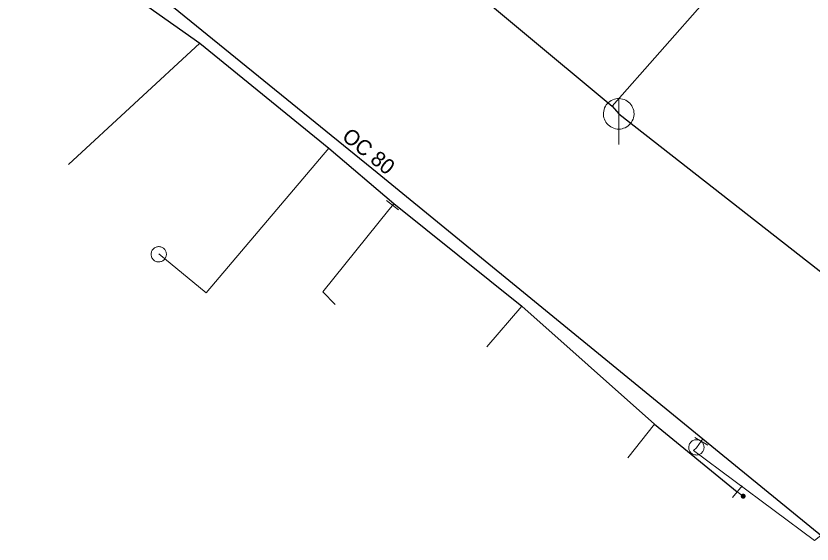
# Model space of a CAD drawing. Extents: x -807203 to -805207, y -993656 to -992505.
# Drawn here: x -806253.1 to -806201.1, y -993114.2 to -993079.6 of the extents above; entities that cross this region are included whole.
import ezdxf

# ---------------------------------------------------------------- set-up
doc = ezdxf.new("R2010")
doc.units = 0
doc.header["$LTSCALE"] = 0.4
for name, color, linetype, lineweight in [('1', 7, 'Continuous', 13), ('11', 7, 'Continuous', 13), ('13', 7, 'Continuous', 13), ('14', 7, 'Continuous', 25), ('17', 7, 'Continuous', 25), ('22', 7, 'Continuous', 13), ('23', 7, 'Continuous', 13), ('34', 7, 'Continuous', 13), ('9', 7, 'Continuous', 13)]:
    doc.layers.add(name, color=color, linetype=linetype, lineweight=lineweight)

msp = doc.modelspace()

# ---------------------------------------------------------------- linework, layer by layer
at = {"layer": '11'}
msp.add_line((-806202.545, -993072.334), (-806214.182, -993085.525), dxfattribs=at)
at = {"layer": '13'}
for p, q in [((-806241.126, -993081.403), (-806249.708, -993089.354)), ((-806220.091, -993098.618), (-806222.371, -993101.277)), ((-806211.407, -993106.321), (-806213.149, -993108.524)), ((-806208.354, -993107.448), (-806208.673, -993107.877))]:
    msp.add_line(p, q, dxfattribs=at)
for points in [[(-806232.688, -993088.282), (-806240.721, -993097.734), (-806243.812, -993095.184)], [(-806228.53, -993092.005), (-806228.541, -993092.017), (-806228.771, -993092.304), (-806233.083, -993097.67), (-806232.282, -993098.499)], [(-806208.673, -993107.877), (-806208.857, -993108.048), (-806200.958, -993113.93), (-806188.421, -993104.047)]]:
    msp.add_lwpolyline(points, dxfattribs=at)
at = {"layer": '14', "lineweight": 13}
for p, q in [((-806208.251, -993107.276), (-806208.354, -993107.448)), ((-806206.008, -993110.745), (-806205.613, -993111.035))]:
    msp.add_line(p, q, dxfattribs=at)
at = {"layer": '14'}
for points in [[(-806254.43, -993051.92), (-806244.407, -993060.288), (-806237.672, -993065.911), (-806232.281, -993070.413), (-806214.182, -993085.525), (-806213.75, -993086.03)], [(-806213.75, -993086.03), (-806174.365, -993116.849), (-806173.301, -993117.667)]]:
    msp.add_lwpolyline(points, dxfattribs=at)
at = {"layer": '14', "lineweight": 13}
msp.add_lwpolyline([(-806228.53, -993092.005), (-806228.521, -993091.993), (-806228.441, -993091.894)], dxfattribs=at)
at = {"layer": '17'}
for points in [[(-806264, -993062.975), (-806257.908, -993068.451), (-806254.907, -993071.059), (-806252.861, -993072.806), (-806252.697, -993072.945), (-806252.545, -993073.07), (-806250.353, -993074.879), (-806241.125, -993081.403), (-806232.688, -993088.282), (-806228.441, -993091.894), (-806220.09, -993098.618), (-806211.407, -993106.321), (-806206.008, -993110.745)], [(-806260.066, -993064.828), (-806248.392, -993074.528), (-806229.53, -993089.861), (-806208.251, -993107.276), (-806200.433, -993113.675), (-806198.425, -993115.318), (-806170.996, -993137.161), (-806169.414, -993138.403), (-806155.574, -993149.442), (-806086.497, -993204.202), (-806063.424, -993223.055)]]:
    msp.add_lwpolyline(points, dxfattribs=at)
at = {"layer": '22'}
msp.add_line((-806213.75, -993088.03), (-806213.749, -993085.03), dxfattribs=at)
msp.add_lwpolyline([(-806212.75, -993086.03), (-806212.755, -993085.921), (-806212.773, -993085.813), (-806212.803, -993085.707), (-806212.843, -993085.606), (-806212.895, -993085.509), (-806212.957, -993085.419), (-806213.029, -993085.336), (-806213.109, -993085.262), (-806213.197, -993085.196), (-806213.291, -993085.141), (-806213.391, -993085.096), (-806213.496, -993085.063), (-806213.603, -993085.041), (-806213.712, -993085.031), (-806213.822, -993085.033), (-806213.93, -993085.047), (-806214.037, -993085.072), (-806214.14, -993085.109), (-806214.238, -993085.158), (-806214.33, -993085.216), (-806214.416, -993085.285), (-806214.493, -993085.362), (-806214.562, -993085.448), (-806214.621, -993085.54), (-806214.669, -993085.638), (-806214.706, -993085.741), (-806214.732, -993085.848), (-806214.746, -993085.956), (-806214.749, -993086.066), (-806214.739, -993086.175), (-806214.718, -993086.282), (-806214.684, -993086.386), (-806214.64, -993086.486), (-806214.585, -993086.581), (-806214.519, -993086.669), (-806214.445, -993086.749), (-806214.362, -993086.821), (-806214.272, -993086.883), (-806214.176, -993086.935), (-806214.074, -993086.976), (-806213.969, -993087.006), (-806213.861, -993087.024), (-806213.751, -993087.03), (-806213.642, -993087.024), (-806213.534, -993087.006), (-806213.429, -993086.977), (-806213.327, -993086.936), (-806213.23, -993086.884), (-806213.14, -993086.822), (-806213.057, -993086.751), (-806212.982, -993086.671), (-806212.917, -993086.583), (-806212.861, -993086.489), (-806212.817, -993086.389), (-806212.783, -993086.285), (-806212.761, -993086.177), (-806212.751, -993086.068)], close=True, dxfattribs=at)
at = {"layer": '23'}
for points in [[(-806243.495, -993094.826), (-806243.538, -993094.795), (-806243.583, -993094.769), (-806243.631, -993094.749), (-806243.681, -993094.733), (-806243.731, -993094.722), (-806243.784, -993094.717), (-806243.836, -993094.717), (-806243.888, -993094.723), (-806243.939, -993094.734), (-806243.989, -993094.75), (-806244.037, -993094.771), (-806244.083, -993094.798), (-806244.125, -993094.828), (-806244.162, -993094.863), (-806244.198, -993094.901), (-806244.229, -993094.946), (-806244.255, -993094.989), (-806244.276, -993095.039), (-806244.292, -993095.087), (-806244.304, -993095.138), (-806244.308, -993095.192), (-806244.308, -993095.244), (-806244.302, -993095.297), (-806244.292, -993095.347), (-806244.275, -993095.396), (-806244.253, -993095.445), (-806244.227, -993095.489), (-806244.196, -993095.531), (-806244.16, -993095.57), (-806244.122, -993095.605), (-806244.08, -993095.636), (-806244.034, -993095.662), (-806243.986, -993095.684), (-806243.937, -993095.7), (-806243.886, -993095.709), (-806243.834, -993095.715), (-806243.781, -993095.715), (-806243.728, -993095.709), (-806243.678, -993095.698)], [(-806244.276, -993095.039), (-806244.292, -993095.087), (-806244.304, -993095.138), (-806244.308, -993095.192), (-806244.308, -993095.244), (-806244.302, -993095.297), (-806244.292, -993095.347), (-806244.275, -993095.396), (-806244.253, -993095.445), (-806244.227, -993095.489), (-806244.196, -993095.531), (-806244.16, -993095.57), (-806244.122, -993095.605), (-806244.08, -993095.636), (-806244.034, -993095.662), (-806243.986, -993095.684), (-806243.937, -993095.7), (-806243.886, -993095.709), (-806243.834, -993095.715), (-806243.781, -993095.715), (-806243.728, -993095.709), (-806243.678, -993095.698), (-806243.629, -993095.683), (-806243.58, -993095.66), (-806243.535, -993095.635), (-806243.493, -993095.603), (-806243.455, -993095.568), (-806243.42, -993095.53), (-806243.39, -993095.487), (-806243.363, -993095.442), (-806243.341, -993095.393), (-806243.326, -993095.344), (-806243.315, -993095.292), (-806243.309, -993095.241), (-806243.311, -993095.188), (-806243.315, -993095.137), (-806243.326, -993095.086), (-806243.342, -993095.035), (-806243.364, -993094.987), (-806243.39, -993094.942)], [(-806243.678, -993095.698), (-806243.629, -993095.683), (-806243.58, -993095.66), (-806243.535, -993095.635), (-806243.493, -993095.603), (-806243.455, -993095.568), (-806243.42, -993095.53), (-806243.39, -993095.487), (-806243.363, -993095.442), (-806243.341, -993095.393), (-806243.326, -993095.344), (-806243.315, -993095.292), (-806243.309, -993095.241), (-806243.311, -993095.188), (-806243.315, -993095.137), (-806243.326, -993095.086), (-806243.342, -993095.035), (-806243.364, -993094.987), (-806243.39, -993094.942), (-806243.422, -993094.9), (-806243.456, -993094.862), (-806243.495, -993094.826), (-806243.538, -993094.795), (-806243.583, -993094.769), (-806243.631, -993094.749), (-806243.681, -993094.733), (-806243.731, -993094.722), (-806243.784, -993094.717), (-806243.836, -993094.717), (-806243.888, -993094.723), (-806243.939, -993094.734), (-806243.989, -993094.75), (-806244.037, -993094.771), (-806244.083, -993094.798), (-806244.125, -993094.828), (-806244.162, -993094.863), (-806244.198, -993094.901), (-806244.229, -993094.946), (-806244.255, -993094.989), (-806244.276, -993095.039)], [(-806243.39, -993094.942), (-806243.422, -993094.9), (-806243.456, -993094.862), (-806243.495, -993094.826)], [(-806208.209, -993108.025), (-806208.193, -993107.977), (-806208.181, -993107.926), (-806208.176, -993107.872), (-806208.176, -993107.82), (-806208.181, -993107.767), (-806208.191, -993107.716), (-806208.207, -993107.667), (-806208.229, -993107.619), (-806208.254, -993107.574), (-806208.285, -993107.532), (-806208.321, -993107.493), (-806208.359, -993107.457), (-806208.4, -993107.426), (-806208.446, -993107.4), (-806208.494, -993107.378), (-806208.543, -993107.361), (-806208.594, -993107.352), (-806208.646, -993107.346), (-806208.699, -993107.345), (-806208.751, -993107.35), (-806208.802, -993107.361), (-806208.851, -993107.376), (-806208.9, -993107.398), (-806208.945, -993107.423), (-806208.988, -993107.455), (-806209.026, -993107.489), (-806209.062, -993107.527), (-806209.092, -993107.57), (-806209.119, -993107.615), (-806209.141, -993107.663), (-806209.157, -993107.712), (-806209.168, -993107.764), (-806209.175, -993107.815), (-806209.173, -993107.868), (-806209.17, -993107.919), (-806209.159, -993107.97), (-806209.143, -993108.021), (-806209.121, -993108.069), (-806209.095, -993108.114)], [(-806208.802, -993107.361), (-806208.851, -993107.376), (-806208.9, -993107.398), (-806208.945, -993107.423), (-806208.988, -993107.455), (-806209.026, -993107.489), (-806209.062, -993107.527), (-806209.092, -993107.57), (-806209.119, -993107.615), (-806209.141, -993107.663), (-806209.157, -993107.712), (-806209.168, -993107.764), (-806209.175, -993107.815), (-806209.173, -993107.868), (-806209.17, -993107.919), (-806209.159, -993107.97), (-806209.143, -993108.021), (-806209.121, -993108.069), (-806209.095, -993108.114), (-806209.064, -993108.156), (-806209.03, -993108.195), (-806208.992, -993108.231), (-806208.95, -993108.263), (-806208.904, -993108.289), (-806208.857, -993108.309), (-806208.807, -993108.326), (-806208.756, -993108.337), (-806208.703, -993108.342), (-806208.651, -993108.343), (-806208.6, -993108.338), (-806208.549, -993108.327), (-806208.499, -993108.312), (-806208.45, -993108.291), (-806208.404, -993108.264), (-806208.362, -993108.234), (-806208.324, -993108.2), (-806208.288, -993108.162), (-806208.257, -993108.118), (-806208.231, -993108.074), (-806208.209, -993108.025)], [(-806208.992, -993108.231), (-806208.95, -993108.263), (-806208.904, -993108.289), (-806208.857, -993108.309), (-806208.807, -993108.326), (-806208.756, -993108.337), (-806208.703, -993108.342), (-806208.651, -993108.343), (-806208.6, -993108.338), (-806208.549, -993108.327), (-806208.499, -993108.312), (-806208.45, -993108.291), (-806208.404, -993108.264), (-806208.362, -993108.234), (-806208.324, -993108.2), (-806208.288, -993108.162), (-806208.257, -993108.118), (-806208.231, -993108.074), (-806208.209, -993108.025), (-806208.193, -993107.977), (-806208.181, -993107.926), (-806208.176, -993107.872), (-806208.176, -993107.82), (-806208.181, -993107.767), (-806208.191, -993107.716), (-806208.207, -993107.667), (-806208.229, -993107.619), (-806208.254, -993107.574), (-806208.285, -993107.532), (-806208.321, -993107.493), (-806208.359, -993107.457), (-806208.4, -993107.426), (-806208.446, -993107.4), (-806208.494, -993107.378), (-806208.543, -993107.361), (-806208.594, -993107.352), (-806208.646, -993107.346), (-806208.699, -993107.345), (-806208.751, -993107.35), (-806208.802, -993107.361)], [(-806209.095, -993108.114), (-806209.064, -993108.156), (-806209.03, -993108.195), (-806208.992, -993108.231)]]:
    msp.add_lwpolyline(points, dxfattribs=at)
at = {"layer": '34'}
for p, q in [((-806228.92, -993091.692), (-806228.14, -993092.318)), ((-806207.924, -993107.704), (-806208.782, -993107.19)), ((-806205.691, -993110.357), (-806206.325, -993111.131))]:
    msp.add_line(p, q, dxfattribs=at)
at = {"layer": '9'}
for points in [[(-806205.739, -993111.035), (-806205.739, -993111.048), (-806205.737, -993111.061), (-806205.734, -993111.074), (-806205.729, -993111.086), (-806205.723, -993111.098), (-806205.716, -993111.109), (-806205.708, -993111.119), (-806205.698, -993111.129), (-806205.688, -993111.137), (-806205.677, -993111.144), (-806205.665, -993111.15), (-806205.653, -993111.155), (-806205.64, -993111.158), (-806205.627, -993111.16), (-806205.614, -993111.162), (-806205.601, -993111.161), (-806205.588, -993111.159), (-806205.575, -993111.156), (-806205.563, -993111.151), (-806205.551, -993111.145), (-806205.54, -993111.138), (-806205.53, -993111.13), (-806205.52, -993111.12), (-806205.512, -993111.11), (-806205.505, -993111.099), (-806205.499, -993111.087), (-806205.494, -993111.075), (-806205.491, -993111.062), (-806205.489, -993111.049), (-806205.487, -993111.036), (-806205.488, -993111.023), (-806205.49, -993111.01), (-806205.493, -993110.997), (-806205.498, -993110.985), (-806205.504, -993110.973), (-806205.511, -993110.962), (-806205.519, -993110.952), (-806205.529, -993110.942), (-806205.539, -993110.934), (-806205.55, -993110.927), (-806205.562, -993110.921), (-806205.574, -993110.916), (-806205.587, -993110.913), (-806205.6, -993110.911), (-806205.613, -993110.91), (-806205.626, -993110.91), (-806205.639, -993110.912), (-806205.652, -993110.915), (-806205.664, -993110.92), (-806205.676, -993110.926), (-806205.687, -993110.933), (-806205.697, -993110.941), (-806205.707, -993110.951), (-806205.715, -993110.961), (-806205.722, -993110.972), (-806205.728, -993110.984), (-806205.733, -993110.996), (-806205.736, -993111.009), (-806205.738, -993111.022)], [(-806205.719, -993111.035), (-806205.72, -993111.046), (-806205.718, -993111.057), (-806205.715, -993111.068), (-806205.711, -993111.078), (-806205.706, -993111.088), (-806205.7, -993111.097), (-806205.693, -993111.106), (-806205.685, -993111.114), (-806205.676, -993111.121), (-806205.667, -993111.127), (-806205.657, -993111.132), (-806205.647, -993111.136), (-806205.636, -993111.139), (-806205.625, -993111.142), (-806205.614, -993111.142), (-806205.603, -993111.142), (-806205.592, -993111.14), (-806205.581, -993111.137), (-806205.571, -993111.133), (-806205.561, -993111.128), (-806205.552, -993111.122), (-806205.543, -993111.115), (-806205.535, -993111.107), (-806205.528, -993111.098), (-806205.522, -993111.089), (-806205.517, -993111.079), (-806205.513, -993111.069), (-806205.51, -993111.058), (-806205.508, -993111.047), (-806205.507, -993111.036), (-806205.507, -993111.025), (-806205.509, -993111.014), (-806205.512, -993111.003), (-806205.516, -993110.993), (-806205.521, -993110.983), (-806205.527, -993110.974), (-806205.534, -993110.965), (-806205.542, -993110.957), (-806205.551, -993110.95), (-806205.56, -993110.944), (-806205.57, -993110.939), (-806205.58, -993110.935), (-806205.591, -993110.932), (-806205.602, -993110.93), (-806205.613, -993110.93), (-806205.624, -993110.929), (-806205.635, -993110.931), (-806205.646, -993110.934), (-806205.656, -993110.938), (-806205.666, -993110.943), (-806205.675, -993110.949), (-806205.684, -993110.956), (-806205.692, -993110.964), (-806205.699, -993110.973), (-806205.705, -993110.982), (-806205.71, -993110.992), (-806205.714, -993111.002), (-806205.717, -993111.013), (-806205.719, -993111.024)], [(-806205.7, -993111.035), (-806205.7, -993111.044), (-806205.699, -993111.053), (-806205.696, -993111.062), (-806205.693, -993111.07), (-806205.689, -993111.078), (-806205.684, -993111.086), (-806205.678, -993111.093), (-806205.672, -993111.099), (-806205.665, -993111.105), (-806205.657, -993111.11), (-806205.649, -993111.114), (-806205.641, -993111.117), (-806205.632, -993111.12), (-806205.623, -993111.121), (-806205.614, -993111.123), (-806205.605, -993111.122), (-806205.596, -993111.121), (-806205.587, -993111.118), (-806205.579, -993111.115), (-806205.571, -993111.111), (-806205.563, -993111.106), (-806205.556, -993111.1), (-806205.55, -993111.094), (-806205.544, -993111.087), (-806205.539, -993111.079), (-806205.535, -993111.071), (-806205.532, -993111.063), (-806205.529, -993111.054), (-806205.528, -993111.045), (-806205.526, -993111.036), (-806205.527, -993111.027), (-806205.528, -993111.018), (-806205.531, -993111.009), (-806205.534, -993111.001), (-806205.538, -993110.993), (-806205.543, -993110.985), (-806205.549, -993110.978), (-806205.555, -993110.972), (-806205.562, -993110.966), (-806205.57, -993110.961), (-806205.578, -993110.957), (-806205.586, -993110.954), (-806205.595, -993110.951), (-806205.604, -993110.95), (-806205.613, -993110.949), (-806205.622, -993110.949), (-806205.631, -993110.95), (-806205.64, -993110.953), (-806205.648, -993110.956), (-806205.656, -993110.96), (-806205.664, -993110.965), (-806205.671, -993110.971), (-806205.677, -993110.977), (-806205.683, -993110.984), (-806205.688, -993110.992), (-806205.692, -993111), (-806205.695, -993111.008), (-806205.698, -993111.017), (-806205.699, -993111.026)], [(-806205.68, -993111.035), (-806205.68, -993111.042), (-806205.679, -993111.049), (-806205.678, -993111.056), (-806205.675, -993111.062), (-806205.672, -993111.068), (-806205.668, -993111.074), (-806205.664, -993111.08), (-806205.659, -993111.085), (-806205.653, -993111.089), (-806205.647, -993111.093), (-806205.641, -993111.096), (-806205.635, -993111.099), (-806205.628, -993111.1), (-806205.621, -993111.103), (-806205.614, -993111.103), (-806205.607, -993111.103), (-806205.6, -993111.101), (-806205.593, -993111.1), (-806205.587, -993111.097), (-806205.58, -993111.094), (-806205.575, -993111.09), (-806205.569, -993111.086), (-806205.564, -993111.081), (-806205.56, -993111.075), (-806205.556, -993111.069), (-806205.553, -993111.063), (-806205.55, -993111.057), (-806205.548, -993111.05), (-806205.547, -993111.043), (-806205.546, -993111.036), (-806205.546, -993111.029), (-806205.547, -993111.022), (-806205.549, -993111.015), (-806205.552, -993111.009), (-806205.555, -993111.002), (-806205.559, -993110.997), (-806205.563, -993110.991), (-806205.568, -993110.986), (-806205.574, -993110.982), (-806205.579, -993110.978), (-806205.586, -993110.975), (-806205.592, -993110.972), (-806205.599, -993110.97), (-806205.606, -993110.969), (-806205.613, -993110.969), (-806205.62, -993110.969), (-806205.627, -993110.969), (-806205.634, -993110.971), (-806205.64, -993110.974), (-806205.646, -993110.977), (-806205.652, -993110.981), (-806205.658, -993110.985), (-806205.663, -993110.99), (-806205.667, -993110.996), (-806205.671, -993111.001), (-806205.674, -993111.008), (-806205.677, -993111.014), (-806205.678, -993111.021), (-806205.68, -993111.028)], [(-806205.66, -993111.035), (-806205.66, -993111.04), (-806205.66, -993111.045), (-806205.659, -993111.05), (-806205.657, -993111.054), (-806205.655, -993111.059), (-806205.652, -993111.063), (-806205.649, -993111.066), (-806205.645, -993111.07), (-806205.642, -993111.073), (-806205.638, -993111.076), (-806205.633, -993111.078), (-806205.629, -993111.08), (-806205.624, -993111.081), (-806205.619, -993111.083), (-806205.614, -993111.083), (-806205.609, -993111.083), (-806205.604, -993111.082), (-806205.599, -993111.081), (-806205.595, -993111.079), (-806205.59, -993111.077), (-806205.586, -993111.074), (-806205.582, -993111.071), (-806205.579, -993111.067), (-806205.576, -993111.064), (-806205.573, -993111.06), (-806205.571, -993111.055), (-806205.569, -993111.051), (-806205.568, -993111.046), (-806205.567, -993111.041), (-806205.566, -993111.036), (-806205.566, -993111.031), (-806205.567, -993111.026), (-806205.568, -993111.021), (-806205.57, -993111.017), (-806205.572, -993111.012), (-806205.575, -993111.008), (-806205.578, -993111.004), (-806205.581, -993111.001), (-806205.585, -993110.998), (-806205.589, -993110.995), (-806205.594, -993110.993), (-806205.598, -993110.991), (-806205.603, -993110.99), (-806205.608, -993110.989), (-806205.613, -993110.989), (-806205.618, -993110.989), (-806205.623, -993110.99), (-806205.628, -993110.99), (-806205.632, -993110.992), (-806205.637, -993110.994), (-806205.641, -993110.997), (-806205.644, -993111), (-806205.648, -993111.003), (-806205.651, -993111.007), (-806205.654, -993111.011), (-806205.656, -993111.016), (-806205.658, -993111.02), (-806205.659, -993111.025), (-806205.66, -993111.03)], [(-806205.64, -993111.035), (-806205.64, -993111.038), (-806205.641, -993111.041), (-806205.64, -993111.043), (-806205.639, -993111.046), (-806205.638, -993111.049), (-806205.636, -993111.051), (-806205.634, -993111.053), (-806205.632, -993111.055), (-806205.63, -993111.057), (-806205.628, -993111.059), (-806205.625, -993111.061), (-806205.622, -993111.062), (-806205.62, -993111.062), (-806205.617, -993111.063), (-806205.614, -993111.063), (-806205.611, -993111.063), (-806205.608, -993111.063), (-806205.605, -993111.062), (-806205.603, -993111.061), (-806205.6, -993111.06), (-806205.598, -993111.058), (-806205.595, -993111.056), (-806205.593, -993111.054), (-806205.592, -993111.052), (-806205.59, -993111.05), (-806205.589, -993111.047), (-806205.587, -993111.044), (-806205.587, -993111.042), (-806205.586, -993111.039), (-806205.585, -993111.036), (-806205.586, -993111.033), (-806205.586, -993111.03), (-806205.587, -993111.027), (-806205.588, -993111.025), (-806205.589, -993111.022), (-806205.591, -993111.02), (-806205.592, -993111.017), (-806205.594, -993111.015), (-806205.597, -993111.014), (-806205.599, -993111.012), (-806205.602, -993111.011), (-806205.604, -993111.01), (-806205.607, -993111.009), (-806205.61, -993111.009), (-806205.613, -993111.008), (-806205.616, -993111.009), (-806205.619, -993111.008), (-806205.621, -993111.01), (-806205.624, -993111.01), (-806205.627, -993111.011), (-806205.629, -993111.013), (-806205.631, -993111.014), (-806205.633, -993111.016), (-806205.635, -993111.019), (-806205.637, -993111.021), (-806205.638, -993111.024), (-806205.639, -993111.026), (-806205.64, -993111.029), (-806205.64, -993111.032)], [(-806205.621, -993111.035), (-806205.621, -993111.037), (-806205.621, -993111.037), (-806205.62, -993111.037), (-806205.62, -993111.039), (-806205.621, -993111.04), (-806205.619, -993111.04), (-806205.619, -993111.04), (-806205.619, -993111.042), (-806205.619, -993111.042), (-806205.618, -993111.043), (-806205.616, -993111.043), (-806205.616, -993111.043), (-806205.616, -993111.044), (-806205.614, -993111.044), (-806205.614, -993111.044), (-806205.613, -993111.044), (-806205.612, -993111.044), (-806205.612, -993111.043), (-806205.611, -993111.043), (-806205.609, -993111.043), (-806205.609, -993111.042), (-806205.609, -993111.042), (-806205.608, -993111.041), (-806205.608, -993111.041), (-806205.606, -993111.04), (-806205.606, -993111.039), (-806205.605, -993111.038), (-806205.605, -993111.038), (-806205.605, -993111.037), (-806205.605, -993111.036), (-806205.605, -993111.035), (-806205.605, -993111.034), (-806205.605, -993111.034), (-806205.606, -993111.033), (-806205.606, -993111.032), (-806205.607, -993111.031), (-806205.607, -993111.031), (-806205.608, -993111.03), (-806205.608, -993111.03), (-806205.609, -993111.029), (-806205.61, -993111.029), (-806205.611, -993111.028), (-806205.611, -993111.028), (-806205.612, -993111.028), (-806205.613, -993111.028), (-806205.614, -993111.028), (-806205.615, -993111.028), (-806205.615, -993111.028), (-806205.616, -993111.029), (-806205.617, -993111.028), (-806205.618, -993111.03), (-806205.618, -993111.03), (-806205.619, -993111.03), (-806205.619, -993111.03), (-806205.62, -993111.032), (-806205.62, -993111.033), (-806205.62, -993111.034), (-806205.621, -993111.034), (-806205.621, -993111.035)]]:
    msp.add_lwpolyline(points, close=True, dxfattribs=at)

# ---------------------------------------------------------------- texts
at = {"layer": '1'}
msp.add_text('OC 80 ', height=1, rotation=321, dxfattribs=at).set_placement((-806231.906, -993087.648))

doc.saveas('drawing.dxf')
